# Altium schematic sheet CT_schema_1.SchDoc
size 468 x 258 mm
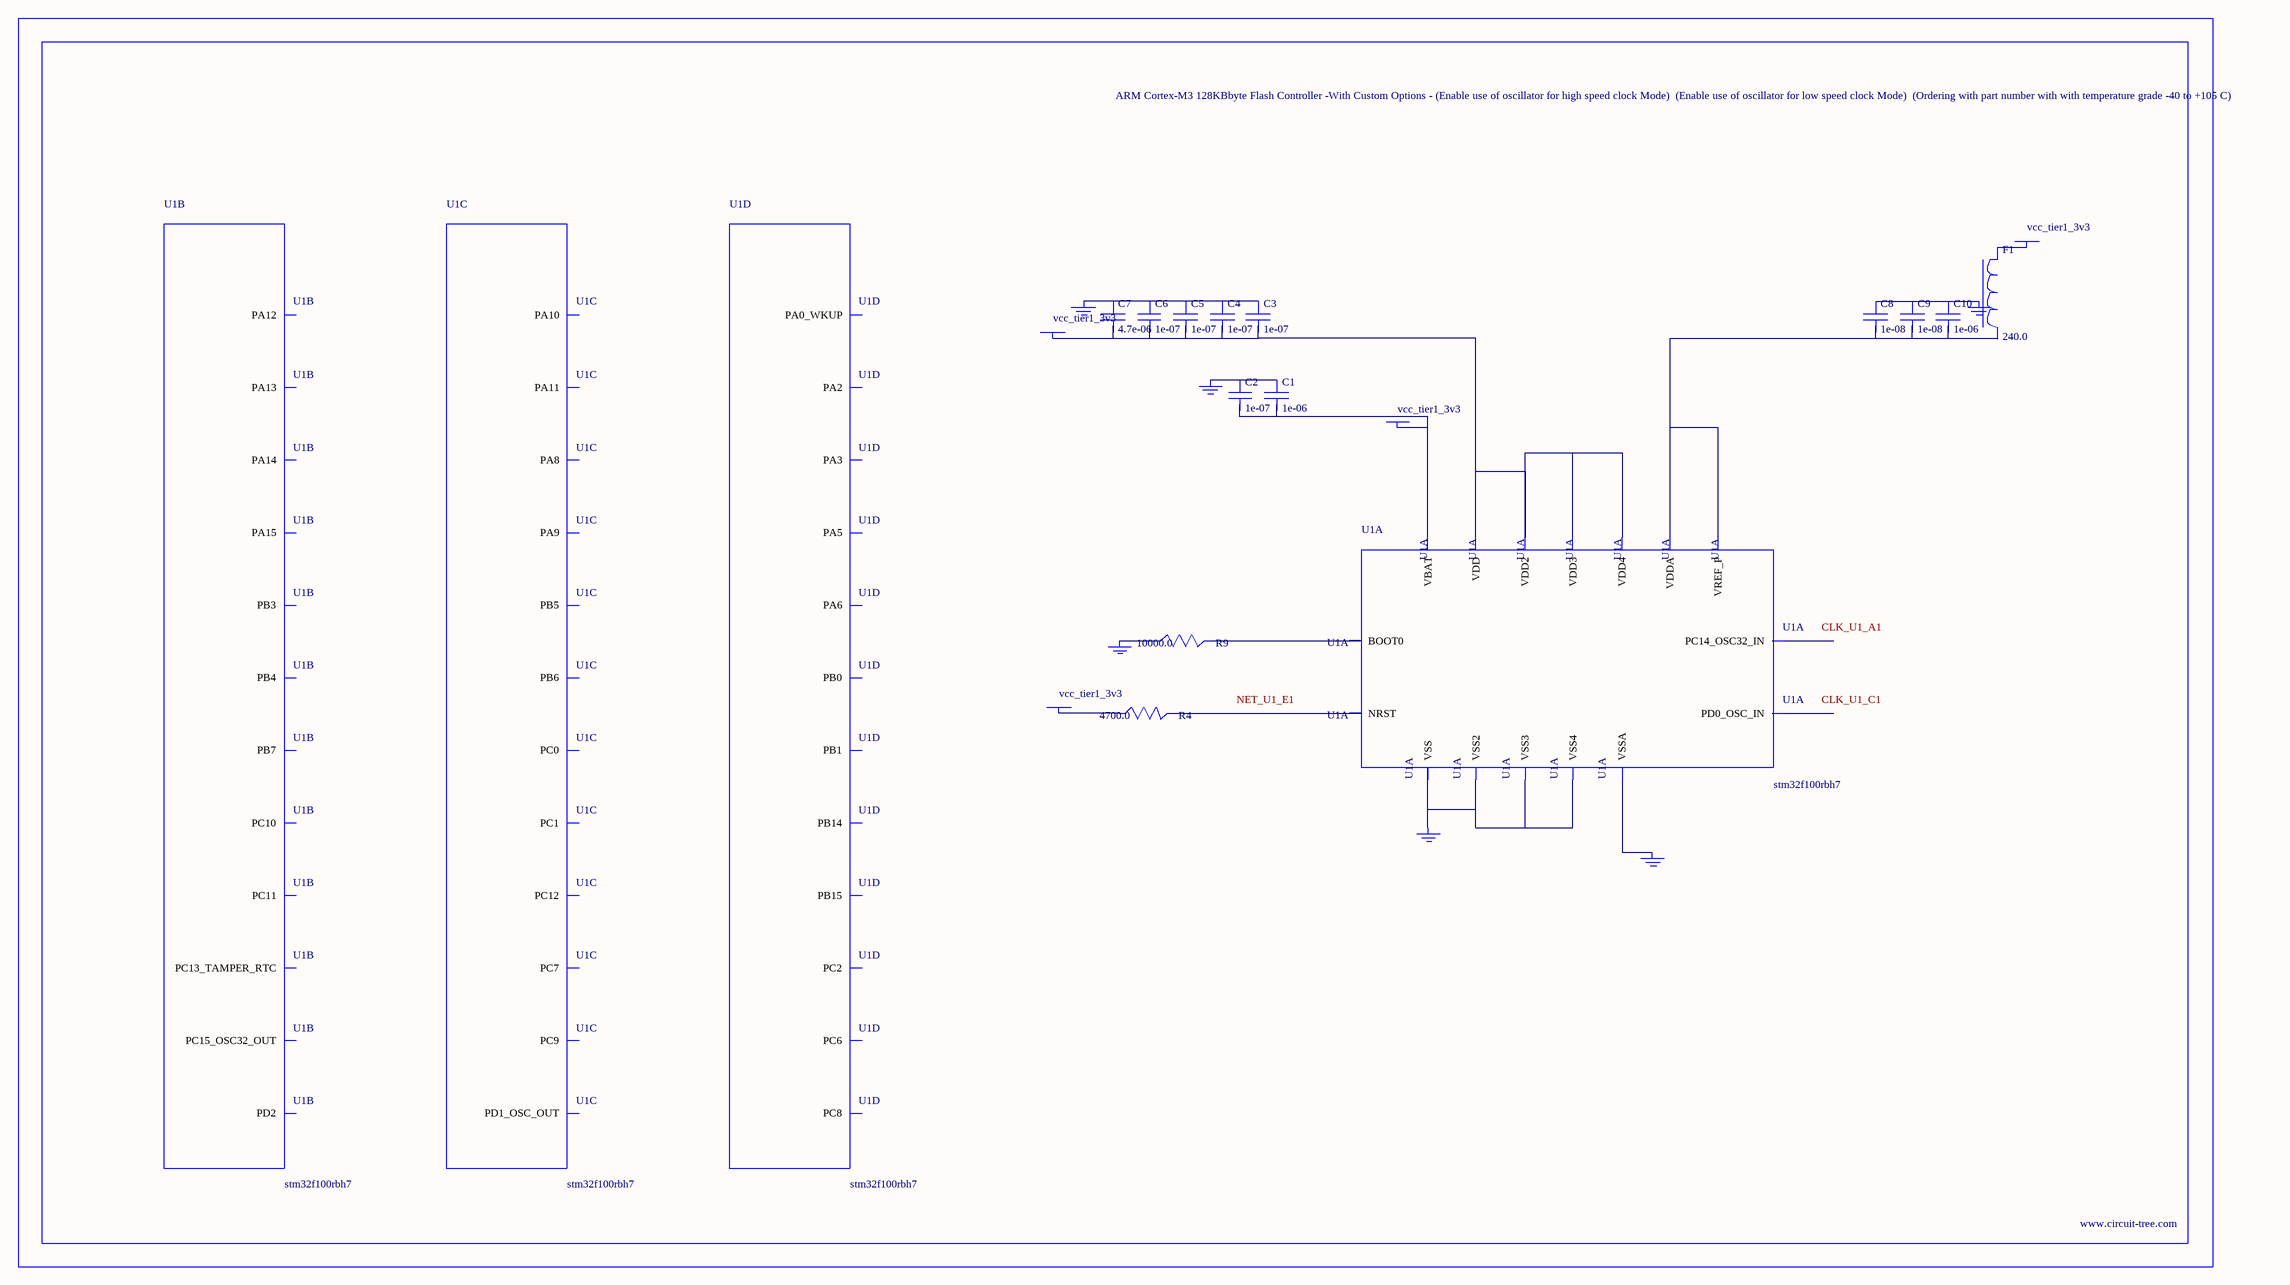
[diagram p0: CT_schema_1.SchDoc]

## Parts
BORDER0  (no value)
C1  1e-06  [C0603]
C2  1e-07  [C0603]
C3  1e-07  [C0603]
C4  1e-07  [C0603]
C5  1e-07  [C0603]
C6  1e-07  [C0603]
C7  4.7e-06  [C0603]
C8  1e-08  [C0603]
C9  1e-08  [C0603]
C10  1e-06  [C0603]
F1  240.0  [L0603]
GND_INSTANCE_0_0  (no value)
GND_INSTANCE_0_1  (no value)
GND_INSTANCE_0_2  (no value)
GND_INSTANCE_0_3  (no value)
GND_INSTANCE_0_4  (no value)
GND_INSTANCE_0_5  (no value)
POWER_INSTANCE_0_0  vcc_tier1_3v3
POWER_INSTANCE_0_1  vcc_tier1_3v3
POWER_INSTANCE_0_2  vcc_tier1_3v3
POWER_INSTANCE_0_3  vcc_tier1_3v3
R4  4700.0  [R0603]
R9  10000.0  [R0603]
U1  stm32f100rbh7  [TFBGA64]  (parts A,B,C,D of 6)

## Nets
NetC1_1: C1.1 C2.1 GND_INSTANCE_0_0.0(GND)
NetC1_2: C1.2 C2.2 POWER_INSTANCE_0_0.0(PWR) U1.B2(VBAT)
NetC3_1: C3.1 C4.1 C5.1 C6.1 C7.1 GND_INSTANCE_0_2.0(GND)
NetC3_2: C3.2 C4.2 C5.2 C6.2 C7.2 POWER_INSTANCE_0_2.0(PWR) U1.D2(VDD) U1.E4(VDD2) U1.E5(VDD3) U1.E6(VDD4)
NetC8_1: C8.1 C9.1 C10.1 GND_INSTANCE_0_1.0(GND)
NetC8_2: C8.2 C9.2 C10.2 U1.G1(VREF_P) U1.H1(VDDA)
NetF1_1: F1.1 POWER_INSTANCE_0_1.0(PWR)
NetGND_INSTANCE_0_3_0: GND_INSTANCE_0_3.0(GND) R9.1
NetGND_INSTANCE_0_4_0: GND_INSTANCE_0_4.0(GND) U1.F1(VSSA)
NetGND_INSTANCE_0_5_0: GND_INSTANCE_0_5.0(GND) U1.C2(VSS) U1.D4(VSS2) U1.D5(VSS3) U1.D6(VSS4)
NetPOWER_INSTANCE_0_3_0: POWER_INSTANCE_0_3.0(PWR) R4.1
NetR4_2: R4.2 U1.E1(NRST)
NetR9_2: R9.2 U1.B4(BOOT0)

Not connected (* = marked no-connect by the designer): F1 2; U1 A1(PC14_OSC32_IN) A2(PC13_TAMPER_RTC) A4(PB4) A5(PB3) A6(PA15) A7(PA14) A8(PA13) B1(PC15_OSC32_OUT) B5(PD2) B6(PC11) B7(PC10) B8(PA12) C1(PD0_OSC_IN) C3(PB7) C4(PB5) C5(PC12) C6(PA10) C7(PA9) C8(PA11) D1(PD1_OSC_OUT) D3(PB6) D7(PA8) D8(PC9) E2(PC1) E3(PC0) E7(PC7) E8(PC8) F2(PC2) F3(PA2) F4(PA5) F5(PB0) F6(PC6) F7(PB15) F8(PB14) G2(PA0_WKUP) G3(PA3) G4(PA6) G5(PB1)

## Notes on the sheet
- Labels drawn without touching a wire or pin: CLK_U1_A1, CLK_U1_C1, NET_U1_E1

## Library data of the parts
BORDER0 = BORDER_PAGE0
C1 C10 = C0603C105K3RACTU
C2-C6 = 06035C104K4Z2A
C7 = GRM188R6YA475KE15D
C8 C9 = 06035C103K4Z2A
F1 = Z0603C241ASMST
GND_INSTANCE_0_0-GND_INSTANCE_0_5 = GND
POWER_INSTANCE_0_0-POWER_INSTANCE_0_3 = PWR
R4 = RC0603JR-074K7L
R9 = RC0603JR-0710KL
